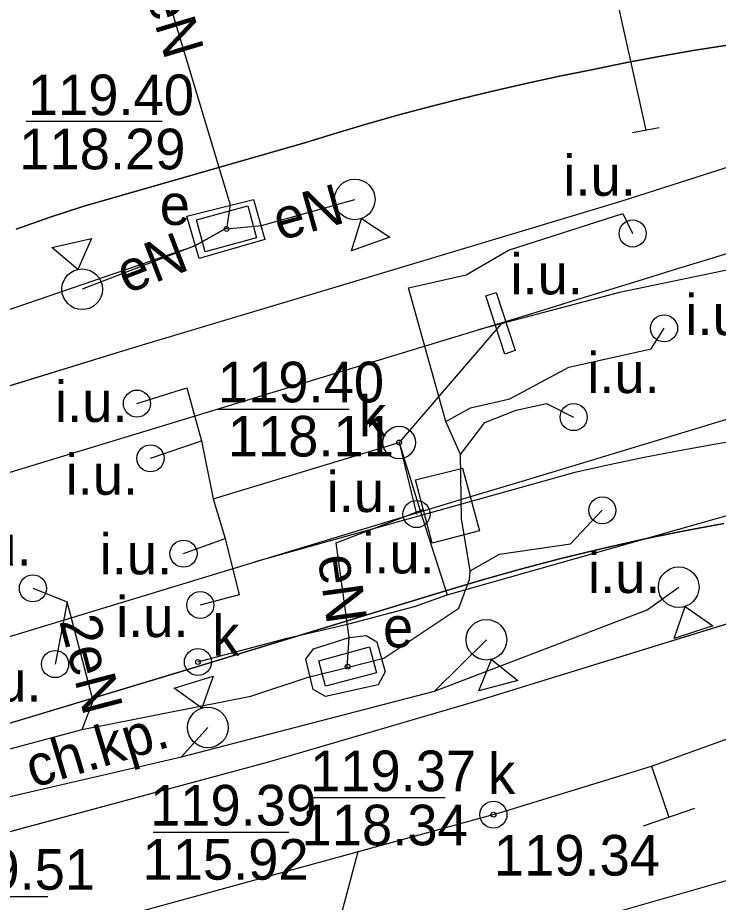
# Model space of a CAD drawing. Extents: x 6432121 to 6432331, y 5662538 to 5662686.
# Drawn here: x 6432205.93 to 6432218.86, y 5662646.9 to 5662663.23 of the extents above; entities that cross this region are included whole.
import ezdxf

# ---------------------------------------------------------------- set-up
doc = ezdxf.new("R2010")
doc.units = 0
for name, color, linetype in [('Warstwa 11', 7, 'Continuous'), ('Warstwa 12', 7, 'Continuous'), ('Warstwa 13', 7, 'Continuous'), ('Warstwa 14', 7, 'Continuous'), ('Warstwa 15', 7, 'Continuous'), ('Warstwa 19', 7, 'Continuous'), ('Warstwa 20', 7, 'Continuous'), ('Warstwa 24', 7, 'Continuous'), ('Warstwa 37', 7, 'Continuous'), ('Warstwa 4', 7, 'Continuous'), ('Warstwa 40', 7, 'Continuous'), ('Warstwa 5', 7, 'Continuous'), ('Warstwa 6', 7, 'Continuous'), ('Warstwa 8', 7, 'Continuous'), ('Warstwa 9', 7, 'Continuous')]:
    doc.layers.add(name, color=color, linetype=linetype)

msp = doc.modelspace()

# ---------------------------------------------------------------- linework, layer by layer
at = {"layer": 'Warstwa 11'}
for points in [[(6432209.05, 5662659.57), (6432210.28, 5662659.88), (6432210.49, 5662659.14), (6432209.28, 5662658.79)], [(6432211.39, 5662651.58), (6432212.05, 5662651.79), (6432212.36, 5662651.83), (6432212.56, 5662651.71), (6432212.71, 5662651.16), (6432212.58, 5662650.92), (6432211.61, 5662650.7), (6432211.38, 5662650.83), (6432211.25, 5662651.39)]]:
    msp.add_lwpolyline(points, close=True, dxfattribs=at)
for centre, radius in [((6432212.97, 5662655.39), 0.3), ((6432214.71, 5662648.52), 0.25)]:
    msp.add_circle(centre, radius, dxfattribs=at)
at = {"layer": 'Warstwa 12'}
for points in [[(6432207.285, 5662667.626), (6432207.6, 5662667.26), (6432209.85, 5662659.78), (6432209.785, 5662659.335)], [(6432220.558, 5662664.988), (6432216.892, 5662664.011), (6432217.526, 5662661.155)], [(6432212.97, 5662655.39), (6432213.402, 5662653.995), (6432213.854, 5662652.579), (6432219.282, 5662654.12), (6432220.373, 5662654.436), (6432224.247, 5662655.447), (6432229.538, 5662656.862), (6432239.665, 5662659.652), (6432244.044, 5662660.848), (6432244.451, 5662661.055)], [(6432190.996, 5662642.041), (6432194.526, 5662643.006), (6432198.018, 5662643.972), (6432203.026, 5662645.328), (6432204.628, 5662645.761), (6432211.976, 5662647.774), (6432214.839, 5662648.562), (6432217.625, 5662649.417), (6432219.194, 5662649.979), (6432224.613, 5662651.789), (6432231.741, 5662654.216), (6432231.921, 5662654.269), (6432237.616, 5662656.187), (6432239.128, 5662656.695), (6432250.011, 5662660.369)], [(6432209.785, 5662659.335), (6432210.43, 5662659.4), (6432212.15, 5662659.88)], [(6432213.83, 5662655.78), (6432213.14, 5662658.25), (6432214.21, 5662658.49), (6432214.99, 5662658.94), (6432217.1, 5662659.62), (6432217.28, 5662659.25)], [(6432202.884, 5662648.217), (6432203.06, 5662648.74), (6432200.45, 5662655.6), (6432200.296, 5662656.008), (6432200.91, 5662656.18), (6432209.2, 5662659.02), (6432209.769, 5662659.344)], [(6432209.769, 5662659.344), (6432209.2, 5662659.02), (6432207.12, 5662658.22)], [(6432214.85, 5662657.58), (6432212.97, 5662655.39)], [(6432213.83, 5662655.78), (6432214.29, 5662656.03), (6432215.01, 5662656.2), (6432216.1, 5662656.78), (6432217.62, 5662657.12), (6432217.86, 5662657.5)], [(6432208.13, 5662656.11), (6432209.05, 5662656.4), (6432209.32, 5662655.42), (6432209.54, 5662654.35), (6432209.76, 5662653.62), (6432210.02, 5662652.58), (6432209.3, 5662652.39)], [(6432214.1, 5662655.17), (6432214.55, 5662655.76), (6432215.13, 5662655.99), (6432215.69, 5662656.11), (6432216.19, 5662655.86)], [(6432214.1, 5662655.17), (6432213.83, 5662655.78)], [(6432208.38, 5662655.1), (6432209.32, 5662655.42)], [(6432209.54, 5662654.35), (6432212.97, 5662655.39)], [(6432212.97, 5662655.39), (6432213.29, 5662654.07)], [(6432214.28, 5662653.02), (6432214.12, 5662653.99), (6432214.1, 5662655.17)], [(6432212.01, 5662651.24), (6432212.05, 5662651.79), (6432211.81, 5662653.54), (6432213.415, 5662654.152)], [(6432214.28, 5662653.02), (6432214.82, 5662653.33), (6432216.13, 5662653.52), (6432216.72, 5662654.14)], [(6432208.99, 5662653.34), (6432209.76, 5662653.62)], [(6432212.01, 5662651.24), (6432212.69, 5662651.41), (6432214.07, 5662652.33), (6432214.27, 5662652.86), (6432214.28, 5662653.02)], [(6432206.21, 5662652.7), (6432206.84, 5662652.45)], [(6432213.62, 5662650.8), (6432217.55, 5662652.3), (6432218.13, 5662652.72)], [(6432158.82, 5662630.77), (6432175.75, 5662635.097), (6432183.256, 5662637.281), (6432187.49, 5662638.459), (6432193.338, 5662639.961), (6432200.302, 5662642.068), (6432202.966, 5662642.795), (6432206.953, 5662643.86), (6432219.613, 5662647.474), (6432231.967, 5662650.923), (6432237.55, 5662652.52)], [(6432209.256, 5662651.339), (6432210.903, 5662651.781), (6432212.04, 5662652.045), (6432213.253, 5662652.362), (6432213.854, 5662652.579)], [(6432206.84, 5662652.45), (6432206.62, 5662651.3)], [(6432207.12, 5662650.09), (6432207.32, 5662650.62), (6432206.84, 5662652.45)], [(6432213.62, 5662650.8), (6432214.58, 5662651.75)], [(6432199.45, 5662647.56), (6432199.93, 5662647.67), (6432200.372, 5662647.811), (6432200.64, 5662647.93), (6432201.39, 5662648.22), (6432202.05, 5662648.68), (6432203.23, 5662649.05), (6432207.12, 5662650.09), (6432210.23, 5662650.71), (6432211.29, 5662651.06), (6432212.01, 5662651.24)], [(6432208.95, 5662649.59), (6432213.62, 5662650.8)], [(6432208.95, 5662649.59), (6432209.44, 5662650.13)], [(6432202.884, 5662648.217), (6432203.52, 5662648.33), (6432208.95, 5662649.59)], [(6432210.04, 5662639.68), (6432212.211, 5662647.839)]]:
    msp.add_lwpolyline(points, dxfattribs=at)
at = {"layer": 'Warstwa 14'}
for p, q in [((6432208.599, 5662661.315), (6432206.083, 5662661.315)), ((6432209.626, 5662656.008), (6432212.049, 5662656.008)), ((6432213.822, 5662648.834), (6432211.294, 5662648.834)), ((6432208.43, 5662648.195), (6432210.932, 5662648.195)), ((6432204.336, 5662647.009), (6432206.484, 5662647.009))]:
    msp.add_line(p, q, dxfattribs=at)
for centre in [(6432209.785, 5662659.335), (6432212.97, 5662655.39), (6432209.256, 5662651.339), (6432209.256, 5662651.339), (6432212.02, 5662651.252), (6432214.71, 5662648.52)]:
    msp.add_circle(centre, 0.045, dxfattribs=at)
at = {"layer": 'Warstwa 19'}
for p, q in [((6432217.625, 5662649.417), (6432217.948, 5662648.471)), ((6432218.422, 5662648.632), (6432217.475, 5662648.309))]:
    msp.add_line(p, q, dxfattribs=at)
at = {"layer": 'Warstwa 20'}
msp.add_line((6432217.772, 5662661.2), (6432217.28, 5662661.11), dxfattribs=at)
at = {"layer": 'Warstwa 24'}
for points in [[(6432214.57, 5662658.1), (6432214.76, 5662658.16), (6432215.11, 5662657.09), (6432214.92, 5662657.02)], [(6432213.27, 5662654.7), (6432214.14, 5662654.92), (6432214.45, 5662653.76), (6432213.58, 5662653.53)]]:
    msp.add_lwpolyline(points, close=True, dxfattribs=at)
for centre in [(6432217.28, 5662659.25), (6432217.86, 5662657.5), (6432208.13, 5662656.11), (6432216.19, 5662655.86), (6432208.38, 5662655.1), (6432213.29, 5662654.07), (6432216.72, 5662654.14), (6432208.99, 5662653.34), (6432206.21, 5662652.7), (6432209.3, 5662652.39), (6432206.62, 5662651.3)]:
    msp.add_circle(centre, 0.25, dxfattribs=at)
at = {"layer": 'Warstwa 37'}
for points in [[(6432214.43, 5662657.47), (6432215.037, 5662657.656), (6432215.643, 5662657.843), (6432216.25, 5662658.029), (6432216.857, 5662658.216), (6432217.464, 5662658.403), (6432218.07, 5662658.589), (6432218.677, 5662658.776), (6432219.283, 5662658.963), (6432219.89, 5662659.15), (6432220.802, 5662659.457), (6432221.709, 5662659.781), (6432222.61, 5662660.121), (6432223.504, 5662660.477), (6432224.392, 5662660.85), (6432225.272, 5662661.239), (6432226.146, 5662661.643), (6432227.012, 5662662.064), (6432227.87, 5662662.5), (6432228.481, 5662662.843), (6432229.084, 5662663.2), (6432229.679, 5662663.572)], [(6432227.088, 5662659.459), (6432226.426, 5662659.442), (6432225.763, 5662659.413), (6432225.101, 5662659.373), (6432224.44, 5662659.322), (6432223.78, 5662659.26), (6432223.344, 5662659.222), (6432222.909, 5662659.18), (6432222.475, 5662659.133), (6432222.041, 5662659.081), (6432221.607, 5662659.024), (6432221.174, 5662658.963), (6432220.742, 5662658.896), (6432220.311, 5662658.826), (6432219.88, 5662658.75), (6432217.04, 5662658.16), (6432214.43, 5662657.47)], [(6432210.31, 5662653.19), (6432211.285, 5662653.484), (6432212.259, 5662653.778), (6432213.234, 5662654.073), (6432214.208, 5662654.367), (6432215.182, 5662654.662), (6432216.157, 5662654.956), (6432217.131, 5662655.251), (6432218.106, 5662655.545), (6432219.08, 5662655.84), (6432219.749, 5662656.04), (6432220.417, 5662656.243), (6432221.083, 5662656.449), (6432221.749, 5662656.659), (6432222.413, 5662656.872), (6432223.077, 5662657.089), (6432223.739, 5662657.309), (6432224.4, 5662657.533), (6432225.06, 5662657.76), (6432225.851, 5662658.053), (6432226.634, 5662658.365)], [(6432137.1, 5662633.64), (6432140.03, 5662634.72), (6432142.7, 5662635.61), (6432144.67, 5662636.22), (6432147.43, 5662637.07), (6432172.26, 5662644.64), (6432209.53, 5662655.98), (6432214.43, 5662657.47)], [(6432227.009, 5662656.117), (6432226.359, 5662656.111), (6432225.709, 5662656.092), (6432225.06, 5662656.06), (6432224.723, 5662656.042), (6432224.386, 5662656.022), (6432224.048, 5662656), (6432223.712, 5662655.975), (6432223.375, 5662655.949), (6432223.038, 5662655.92), (6432222.702, 5662655.889), (6432222.366, 5662655.856), (6432222.03, 5662655.82), (6432221.378, 5662655.743), (6432220.728, 5662655.658), (6432220.078, 5662655.565), (6432219.43, 5662655.465), (6432218.783, 5662655.356), (6432218.137, 5662655.239), (6432217.493, 5662655.114), (6432216.851, 5662654.981), (6432216.21, 5662654.84), (6432210.31, 5662653.19)], [(6432138.97, 5662631.22), (6432139.487, 5662631.415), (6432140.004, 5662631.607), (6432140.523, 5662631.795), (6432141.043, 5662631.981), (6432141.565, 5662632.163), (6432142.087, 5662632.342), (6432142.61, 5662632.518), (6432143.135, 5662632.69), (6432143.66, 5662632.86), (6432144.181, 5662633.026), (6432144.702, 5662633.191), (6432145.223, 5662633.355), (6432145.745, 5662633.517), (6432146.267, 5662633.678), (6432146.79, 5662633.838), (6432147.313, 5662633.997), (6432147.836, 5662634.154), (6432148.36, 5662634.31), (6432173.01, 5662641.84), (6432210.31, 5662653.19)]]:
    msp.add_lwpolyline(points, dxfattribs=at)
at = {"layer": 'Warstwa 4'}
for points in [[(6432209.23, 5662659.5), (6432210.18, 5662659.76), (6432210.34, 5662659.17), (6432209.39, 5662658.91)], [(6432211.49, 5662651.36), (6432212.42, 5662651.62), (6432212.55, 5662651.14), (6432211.61, 5662650.89)]]:
    msp.add_lwpolyline(points, close=True, dxfattribs=at)
for centre, radius in [((6432212.97, 5662655.39), 0.3), ((6432209.256, 5662651.339), 0.25), ((6432214.71, 5662648.52), 0.25)]:
    msp.add_circle(centre, radius, dxfattribs=at)
at = {"layer": 'Warstwa 40'}
for points in [[(6432212.277, 5662659.527), (6432212.799, 5662659.183), (6432212.093, 5662658.93)], [(6432207.038, 5662658.586), (6432206.562, 5662658.992), (6432207.294, 5662659.156)], [(6432218.248, 5662652.364), (6432218.761, 5662652.007), (6432218.049, 5662651.771)], [(6432214.675, 5662651.387), (6432215.163, 5662650.998), (6432214.438, 5662650.809)], [(6432209.328, 5662650.488), (6432208.82, 5662650.853), (6432209.536, 5662651.077)]]:
    msp.add_lwpolyline(points, close=True, dxfattribs=at)
for centre in [(6432212.15, 5662659.88), (6432207.12, 5662658.22), (6432218.13, 5662652.72), (6432214.58, 5662651.75), (6432209.44, 5662650.13)]:
    msp.add_circle(centre, 0.375, dxfattribs=at)
at = {"layer": 'Warstwa 6'}
for points in [[(6432219.029, 5662662.729), (6432218.399, 5662662.63), (6432217.771, 5662662.521), (6432217.144, 5662662.401), (6432216.52, 5662662.27), (6432215.927, 5662662.152), (6432215.336, 5662662.026), (6432214.746, 5662661.892), (6432214.159, 5662661.751), (6432213.573, 5662661.602), (6432212.989, 5662661.445), (6432212.407, 5662661.281), (6432211.827, 5662661.109), (6432211.25, 5662660.93), (6432207.13, 5662659.75), (6432206.513, 5662659.544), (6432205.899, 5662659.332)], [(6432188.05, 5662650.99), (6432208.05, 5662657.14), (6432211.99, 5662658.32), (6432217.07, 5662659.85), (6432220.49, 5662660.94)], [(6432218.96, 5662653.896), (6432218.204, 5662653.754), (6432217.45, 5662653.598), (6432216.699, 5662653.429), (6432215.952, 5662653.247), (6432215.208, 5662653.051), (6432214.467, 5662652.842), (6432213.73, 5662652.62), (6432208.93, 5662651.16), (6432195.12, 5662646.99)], [(6432205.53, 5662648.14), (6432210.54, 5662649.49), (6432214.41, 5662650.62), (6432220.13, 5662652.39)]]:
    msp.add_lwpolyline(points, dxfattribs=at)
at = {"layer": 'Warstwa 8'}
for p, q in [((6432217.771, 5662662.521), (6432218.399, 5662662.63)), ((6432218.399, 5662662.63), (6432219.029, 5662662.729)), ((6432217.144, 5662662.401), (6432217.771, 5662662.521)), ((6432216.52, 5662662.27), (6432217.144, 5662662.401)), ((6432215.336, 5662662.026), (6432215.927, 5662662.152)), ((6432215.927, 5662662.152), (6432216.52, 5662662.27)), ((6432214.746, 5662661.892), (6432215.336, 5662662.026)), ((6432214.159, 5662661.751), (6432214.746, 5662661.892)), ((6432213.573, 5662661.602), (6432214.159, 5662661.751)), ((6432212.989, 5662661.445), (6432213.573, 5662661.602)), ((6432212.407, 5662661.281), (6432212.989, 5662661.445)), ((6432211.827, 5662661.109), (6432212.407, 5662661.281)), ((6432211.25, 5662660.93), (6432211.827, 5662661.109)), ((6432207.13, 5662659.75), (6432211.25, 5662660.93)), ((6432217.07, 5662659.85), (6432220.49, 5662660.94)), ((6432211.99, 5662658.32), (6432217.07, 5662659.85)), ((6432206.513, 5662659.544), (6432207.13, 5662659.75)), ((6432205.899, 5662659.332), (6432206.513, 5662659.544)), ((6432208.05, 5662657.14), (6432211.99, 5662658.32)), ((6432188.05, 5662650.99), (6432208.05, 5662657.14)), ((6432218.204, 5662653.754), (6432218.96, 5662653.896)), ((6432217.45, 5662653.598), (6432218.204, 5662653.754)), ((6432216.699, 5662653.429), (6432217.45, 5662653.598)), ((6432215.952, 5662653.247), (6432216.699, 5662653.429)), ((6432215.208, 5662653.051), (6432215.952, 5662653.247)), ((6432214.467, 5662652.842), (6432215.208, 5662653.051)), ((6432213.73, 5662652.62), (6432214.467, 5662652.842)), ((6432208.93, 5662651.16), (6432213.73, 5662652.62)), ((6432214.41, 5662650.62), (6432220.13, 5662652.39)), ((6432195.12, 5662646.99), (6432208.93, 5662651.16)), ((6432210.54, 5662649.49), (6432214.41, 5662650.62)), ((6432205.53, 5662648.14), (6432210.54, 5662649.49))]:
    msp.add_line(p, q, dxfattribs=at)
at = {"layer": 'Warstwa 9'}
for p, q in [((6432217.771, 5662662.521), (6432218.399, 5662662.63)), ((6432218.399, 5662662.63), (6432219.029, 5662662.729)), ((6432217.144, 5662662.401), (6432217.771, 5662662.521)), ((6432216.52, 5662662.27), (6432217.144, 5662662.401)), ((6432215.336, 5662662.026), (6432215.927, 5662662.152)), ((6432215.927, 5662662.152), (6432216.52, 5662662.27)), ((6432214.746, 5662661.892), (6432215.336, 5662662.026)), ((6432214.159, 5662661.751), (6432214.746, 5662661.892)), ((6432213.573, 5662661.602), (6432214.159, 5662661.751)), ((6432212.989, 5662661.445), (6432213.573, 5662661.602)), ((6432212.407, 5662661.281), (6432212.989, 5662661.445)), ((6432211.827, 5662661.109), (6432212.407, 5662661.281)), ((6432211.25, 5662660.93), (6432211.827, 5662661.109)), ((6432207.13, 5662659.75), (6432211.25, 5662660.93)), ((6432217.07, 5662659.85), (6432220.49, 5662660.94)), ((6432211.99, 5662658.32), (6432217.07, 5662659.85)), ((6432206.513, 5662659.544), (6432207.13, 5662659.75)), ((6432205.899, 5662659.332), (6432206.513, 5662659.544)), ((6432208.05, 5662657.14), (6432211.99, 5662658.32)), ((6432188.05, 5662650.99), (6432208.05, 5662657.14)), ((6432218.204, 5662653.754), (6432218.96, 5662653.896)), ((6432217.45, 5662653.598), (6432218.204, 5662653.754)), ((6432216.699, 5662653.429), (6432217.45, 5662653.598)), ((6432215.952, 5662653.247), (6432216.699, 5662653.429)), ((6432215.208, 5662653.051), (6432215.952, 5662653.247)), ((6432214.467, 5662652.842), (6432215.208, 5662653.051)), ((6432213.73, 5662652.62), (6432214.467, 5662652.842)), ((6432208.93, 5662651.16), (6432213.73, 5662652.62)), ((6432214.41, 5662650.62), (6432220.13, 5662652.39)), ((6432195.12, 5662646.99), (6432208.93, 5662651.16)), ((6432210.54, 5662649.49), (6432214.41, 5662650.62)), ((6432205.53, 5662648.14), (6432210.54, 5662649.49))]:
    msp.add_line(p, q, dxfattribs=at)

# ---------------------------------------------------------------- texts
at = {"layer": 'Warstwa 13'}
for s, rotation, p in [('3eN', 286.7425, (6432208.132, 5662664.19)), ('eN', 15.5902, (6432210.765, 5662659.114)), ('eN', 21.039, (6432207.933, 5662658.131)), ('eN', 277.81, (6432211.467, 5662653.281)), ('2eN', 284.697, (6432206.691, 5662652.098))]:
    msp.add_text(s, height=0.75, rotation=rotation, dxfattribs=at).set_placement(p)
at = {"layer": 'Warstwa 14'}
for s, p in [('118.29', (6432205.958, 5662660.435)), ('118.11', (6432209.806, 5662655.133)), ('118.34', (6432211.169, 5662647.954)), ('115.92', (6432208.232, 5662647.32))]:
    msp.add_text(s, height=0.75, dxfattribs=at).set_placement(p)
at = {"layer": 'Warstwa 15'}
for s, p in [('119.40', (6432206.116, 5662661.435)), ('119.40', (6432209.624, 5662656.133)), ('119.37', (6432211.324, 5662648.954)), ('119.39', (6432208.372, 5662648.32)), ('119.34', (6432214.718, 5662647.396)), ('119.51', (6432204.291, 5662647.134))]:
    msp.add_text(s, height=0.75, dxfattribs=at).set_placement(p)
at = {"layer": 'Warstwa 24'}
for p in [(6432216.002, 5662659.947), (6432215.024, 5662658.126), (6432218.253, 5662657.374), (6432216.441, 5662656.304), (6432206.619, 5662655.772), (6432206.814, 5662654.427), (6432211.632, 5662654.108), (6432204.849, 5662653.115), (6432207.442, 5662652.958), (6432212.289, 5662652.973), (6432216.455, 5662652.613), (6432207.746, 5662651.798), (6432205.031, 5662650.607)]:
    msp.add_text('i.u.', height=0.75, dxfattribs=at).set_placement(p)
at = {"layer": 'Warstwa 5'}
for s, p in [('e', (6432208.552, 5662659.408)), ('k', (6432212.226, 5662655.505)), ('k', (6432209.52, 5662651.454)), ('e', (6432212.672, 5662651.608)), ('k', (6432214.611, 5662648.904))]:
    msp.add_text(s, height=0.75, dxfattribs=at).set_placement(p)
at = {"layer": 'Warstwa 9'}
msp.add_text('ch.kp.', height=0.75, rotation=16.7991, dxfattribs=at).set_placement((6432206.212, 5662649.01))

doc.saveas('drawing.dxf')
